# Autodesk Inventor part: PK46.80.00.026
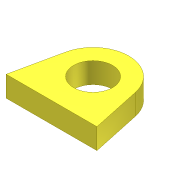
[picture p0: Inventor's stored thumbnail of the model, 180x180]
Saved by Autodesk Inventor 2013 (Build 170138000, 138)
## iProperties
Created: 2005-05
Part Number: PK46.80.00.026
Material: Steel, Mild
Document SubType Name: Modeling
Designer: salex
Manufacturer: Standard
Standards Organization: Custom
Density: 7.86 g/cm^3
Mass: 314.847 g
Surface Area: 100.676 cm^2
Volume: 40.0568 cm^3
Author: salex
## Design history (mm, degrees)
sketch "Эскиз1"
  geometry: L1 (-35, -32)-(35, -32); L2 (35, -32)-(26.887, 5.775); L3 (-35, -32)-(-26.887, 5.775); C1 r 15 at (0, 0); A1 r 27.5 centre (0, 0) between (26.887, 5.775) and (-26.887, 5.775)
  constraints: 6 end point, 2 centre point, 2 point on circle, 2 tangent, 1 coincident, 1 equal length, 1 horizontal, 1 other
  dimensions: "d0" = 32 distance from line of L1 C1.centre; "d1" = 27.5 radius of A1; "d2" = 70 distance of L1.start L1.end; "d3" = 30 diameter of C1
extrude "Выдавливание1" new body sketch "Эскиз1" distance "d4" = 16; taper "d5" = 0 deg
body "Solid1"
